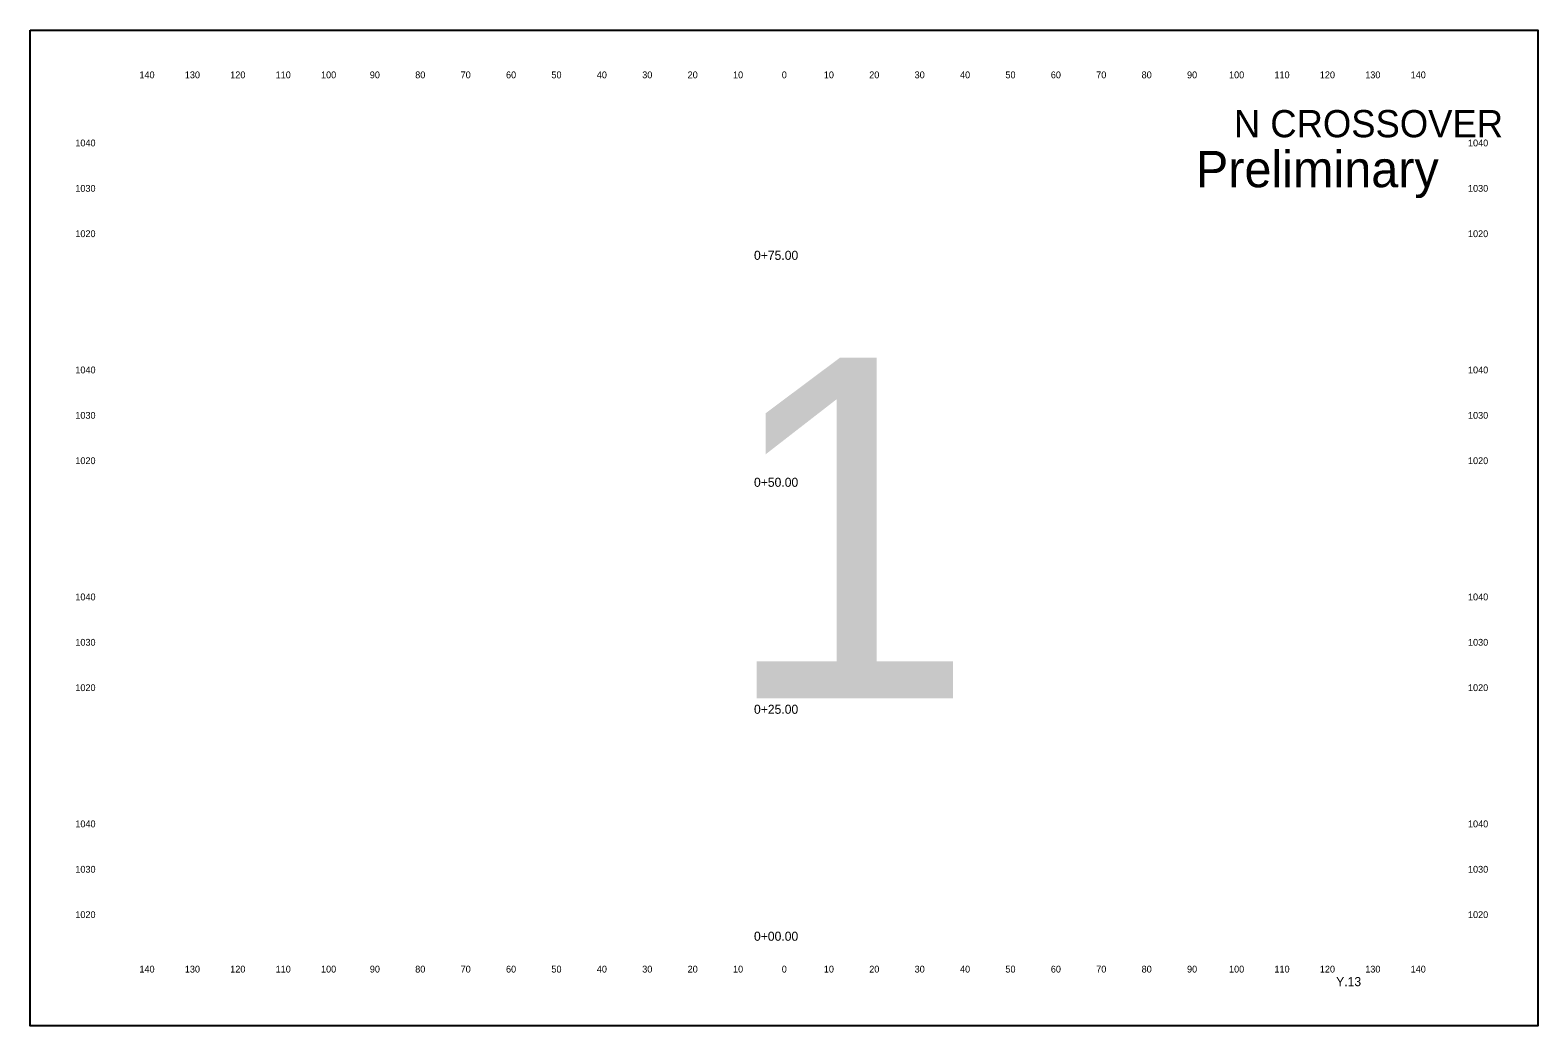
# Model space of a CAD drawing. Extents: x 10123 to 14767, y 9730 to 9950.
# Drawn here: x 10123.2 to 10455.3, y 9730.3 to 9949.6 of the extents above; entities that cross this region are included whole.
import ezdxf

# ---------------------------------------------------------------- set-up
doc = ezdxf.new("R2010")
doc.units = 0
for name, color, linetype in [('dsnTextCpn', 7, 'Continuous'), ('dsnTextCpnTitleSheetLocDesc', 7, 'Continuous'), ('dsnTextCpnTitleSheetPIN', 7, 'Continuous'), ('dsnTextCpnTitleSheetWorkType', 7, 'Continuous')]:
    doc.layers.add(name, color=color, linetype=linetype)

msp = doc.modelspace()

# ---------------------------------------------------------------- linework, layer by layer
at = {"layer": 'dsnTextCpnTitleSheetWorkType'}
msp.add_lwpolyline([(10123.21, 9949.6), (10455.29, 9949.6), (10455.29, 9730.26), (10123.21, 9730.26)], close=True, dxfattribs=at)

# ---------------------------------------------------------------- texts
at = {"layer": 'dsnTextCpn'}
for s, height, p in [('140', 1.5, (10147.27, 9939)), ('130', 1.5, (10157.27, 9939)), ('120', 1.5, (10167.27, 9939)), ('110', 1.5, (10177.27, 9939)), ('100', 1.5, (10187.27, 9939)), ('90', 1.5, (10198.02, 9939)), ('80', 1.5, (10208.02, 9939)), ('70', 1.5, (10218.02, 9939)), ('60', 1.5, (10228.02, 9939)), ('50', 1.5, (10238.02, 9939)), ('40', 1.5, (10248.02, 9939)), ('30', 1.5, (10258.02, 9939)), ('20', 1.5, (10268.02, 9939)), ('10', 1.5, (10278.02, 9939)), ('0', 1.5, (10288.76, 9939)), ('0', 1.5, (10288.76, 9939)), ('10', 1.5, (10298.02, 9939)), ('20', 1.5, (10308.02, 9939)), ('30', 1.5, (10318.02, 9939)), ('40', 1.5, (10328.02, 9939)), ('50', 1.5, (10338.02, 9939)), ('60', 1.5, (10348.02, 9939)), ('70', 1.5, (10358.02, 9939)), ('80', 1.5, (10368.02, 9939)), ('90', 1.5, (10378.02, 9939)), ('100', 1.5, (10387.27, 9939)), ('110', 1.5, (10397.27, 9939)), ('120', 1.5, (10407.27, 9939)), ('130', 1.5, (10417.27, 9939)), ('140', 1.5, (10427.27, 9939)), ('N CROSSOVER', 6, (10388.34, 9926)), ('1040', 1.5, (10133.15, 9924)), ('1040', 1.5, (10439.9, 9924)), ('1030', 1.5, (10133.15, 9914)), ('1030', 1.5, (10439.9, 9914)), ('1020', 1.5, (10133.15, 9904)), ('1020', 1.5, (10439.9, 9904)), ('0+75.00', 2, (10282.64, 9899)), ('1040', 1.5, (10133.15, 9874)), ('1040', 1.5, (10439.9, 9874)), ('1030', 1.5, (10133.15, 9864)), ('1030', 1.5, (10439.9, 9864)), ('1020', 1.5, (10133.15, 9854)), ('1020', 1.5, (10439.9, 9854)), ('0+50.00', 2, (10282.64, 9849)), ('1040', 1.5, (10133.15, 9824)), ('1040', 1.5, (10439.9, 9824)), ('1030', 1.5, (10133.15, 9814)), ('1030', 1.5, (10439.9, 9814)), ('1020', 1.5, (10133.15, 9804)), ('1020', 1.5, (10439.9, 9804)), ('0+25.00', 2, (10282.64, 9799)), ('1040', 1.5, (10133.15, 9774)), ('1040', 1.5, (10439.9, 9774)), ('1030', 1.5, (10133.15, 9764)), ('1030', 1.5, (10439.9, 9764)), ('1020', 1.5, (10133.15, 9754)), ('1020', 1.5, (10439.9, 9754)), ('0+00.00', 2, (10282.64, 9749)), ('140', 1.5, (10147.27, 9742)), ('130', 1.5, (10157.27, 9742)), ('120', 1.5, (10167.27, 9742)), ('110', 1.5, (10177.27, 9742)), ('100', 1.5, (10187.27, 9742)), ('90', 1.5, (10198.02, 9742)), ('80', 1.5, (10208.02, 9742)), ('70', 1.5, (10218.02, 9742)), ('60', 1.5, (10228.02, 9742)), ('50', 1.5, (10238.02, 9742)), ('40', 1.5, (10248.02, 9742)), ('30', 1.5, (10258.02, 9742)), ('20', 1.5, (10268.02, 9742)), ('10', 1.5, (10278.02, 9742)), ('0', 1.5, (10288.76, 9742)), ('0', 1.5, (10288.76, 9742)), ('10', 1.5, (10298.02, 9742)), ('20', 1.5, (10308.02, 9742)), ('30', 1.5, (10318.02, 9742)), ('40', 1.5, (10328.02, 9742)), ('50', 1.5, (10338.02, 9742)), ('60', 1.5, (10348.02, 9742)), ('70', 1.5, (10358.02, 9742)), ('80', 1.5, (10368.02, 9742)), ('90', 1.5, (10378.02, 9742)), ('100', 1.5, (10387.27, 9742)), ('110', 1.5, (10397.27, 9742)), ('120', 1.5, (10407.27, 9742)), ('130', 1.5, (10417.27, 9742)), ('140', 1.5, (10427.27, 9742))]:
    msp.add_text(s, height=height, dxfattribs=at).set_placement(p)
at = {"layer": 'dsnTextCpnTitleSheetLocDesc'}
msp.add_text('Preliminary', height=8, dxfattribs=at).set_placement((10379.97, 9915))
at = {"layer": 'dsnTextCpnTitleSheetPIN'}
msp.add_text('Y.13', height=2, dxfattribs=at).set_placement((10410.87, 9739))
at = {"layer": 'dsnTextCpnTitleSheetWorkType'}
msp.add_text('1', height=75, dxfattribs=at).set_placement((10275.6, 9802.43))

doc.saveas('drawing.dxf')
